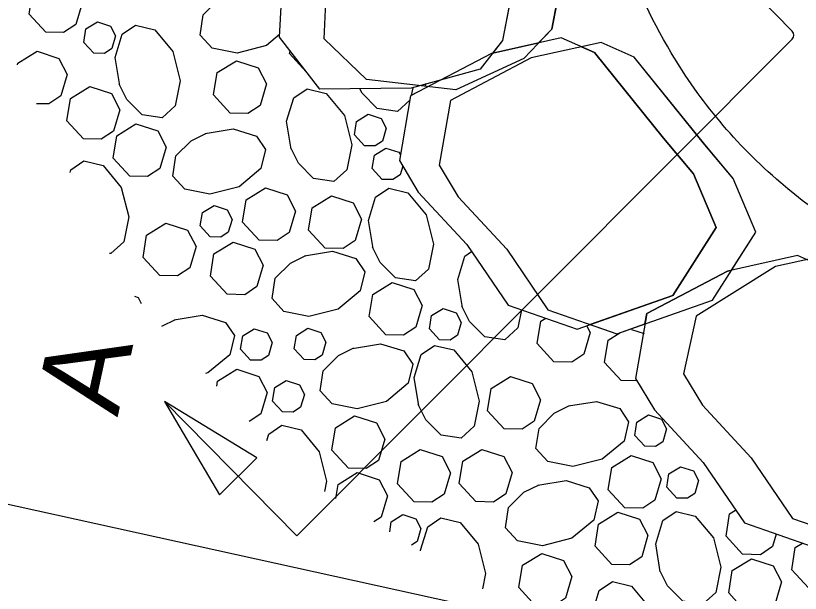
# Model space of a CAD drawing. Extents: x 2126110 to 2128246, y 1804858 to 1811658.
# Drawn here: x 2126424.9 to 2126648.9, y 1809146 to 1809310.8 of the extents above; entities that cross this region are included whole.
import ezdxf

# ---------------------------------------------------------------- set-up
doc = ezdxf.new("R2010")
doc.units = 0
for name, color, linetype in [('1', 7, 'Continuous'), ('DET-EARTH', 7, 'Continuous'), ('Old_Level_1', 7, 'Continuous'), ('Old_Level_41', 7, 'Continuous')]:
    doc.layers.add(name, color=color, linetype=linetype)

msp = doc.modelspace()

# ---------------------------------------------------------------- linework, layer by layer
at = {"layer": '1'}
for p, q in [((2126646.62, 1809306.41), (2126606.59, 1809347.5)), ((2126639.29, 1809123.78), (2126180.41, 1809224.52))]:
    msp.add_line(p, q, dxfattribs=at)
msp.add_lwpolyline([(2126467.4, 1809200.8), (2126505.18, 1809162.41), (2126646.61, 1809304.18)], dxfattribs=at)
msp.add_lwpolyline([(2126493.79, 1809184.68), (2126467.4, 1809200.8), (2126483.09, 1809174.16)], close=True, dxfattribs=at)
msp.add_arc((2126645.48, 1809305.3), 1.59, 315.0669, 44.2554, dxfattribs=at)
at = {"layer": 'DET-EARTH'}
for points in [[(2126500.75, 1809315.15), (2126505.91, 1809334.91), (2126508.16, 1809355.71), (2126522.28, 1809371.01), (2126550.92, 1809375.43), (2126570.93, 1809364.18), (2126572.45, 1809347.61), (2126569.75, 1809334.6), (2126563.89, 1809303.76), (2126557.5, 1809295.61), (2126537.84, 1809290.12), (2126537.84, 1809290.12), (2126511.78, 1809289.89), (2126500.23, 1809304.71), (2126500.75, 1809315.15)], [(2126513.47, 1809314.7), (2126516.16, 1809334.1), (2126522.49, 1809353.22), (2126533.93, 1809366.05), (2126564.43, 1809365.63), (2126581.7, 1809355.74), (2126585.18, 1809347.16), (2126583.83, 1809337.85), (2126577.97, 1809307.02), (2126569.94, 1809298.61), (2126550.56, 1809289.66), (2126550.56, 1809289.66), (2126525.08, 1809292.59), (2126512.96, 1809304.26), (2126513.47, 1809314.7)], [(2126539.84, 1809260.5), (2126553.7, 1809245.52), (2126565.5, 1809228.24), (2126585.16, 1809221.41), (2126612.51, 1809231.03), (2126624.85, 1809250.39), (2126618.37, 1809265.71), (2126609.85, 1809275.91), (2126590.13, 1809300.34), (2126580.66, 1809304.51), (2126560.72, 1809300.09), (2126560.72, 1809300.09), (2126537.65, 1809287.98), (2126534.45, 1809269.47), (2126539.84, 1809260.5)], [(2126551.21, 1809259.18), (2126565.08, 1809244.2), (2126576.87, 1809226.92), (2126596.53, 1809220.09), (2126623.88, 1809229.71), (2126636.22, 1809249.07), (2126629.74, 1809264.39), (2126621.22, 1809274.59), (2126601.5, 1809299.02), (2126592.03, 1809303.19), (2126572.09, 1809298.77), (2126572.09, 1809298.77), (2126549.02, 1809286.66), (2126545.82, 1809268.15), (2126551.21, 1809259.18)], [(2126620.99, 1809199.66), (2126634.85, 1809184.68), (2126646.65, 1809167.39), (2126666.31, 1809160.57), (2126693.66, 1809170.19), (2126706, 1809189.54), (2126699.52, 1809204.86), (2126691, 1809215.07), (2126671.28, 1809239.49), (2126661.81, 1809243.67), (2126641.87, 1809239.24), (2126641.87, 1809239.24), (2126619.16, 1809225.06), (2126615.6, 1809208.63), (2126620.99, 1809199.66)], [(2126607.26, 1809198.38), (2126621.13, 1809183.39), (2126632.93, 1809166.11), (2126652.59, 1809159.29), (2126679.94, 1809168.91), (2126692.27, 1809188.26), (2126685.8, 1809203.58), (2126677.27, 1809213.79), (2126657.56, 1809238.21), (2126648.08, 1809242.38), (2126628.15, 1809237.96), (2126628.15, 1809237.96), (2126605.07, 1809225.86), (2126601.87, 1809207.34), (2126607.26, 1809198.38)]]:
    msp.add_lwpolyline(points, dxfattribs=at)
msp.add_spline([(2126607.67, 1809405.83), (2126618.41, 1809454.94), (2126650.78, 1809501.03), (2126688.47, 1809521.66), (2126738.85, 1809522.03), (2126769.82, 1809494.4), (2126754.53, 1809276.75), (2126715.26, 1809236.01), (2126643.36, 1809263.1), (2126612.06, 1809300.25), (2126598.49, 1809332.37), (2126607.32, 1809404.19)], degree=3, dxfattribs=at)
at = {"layer": 'Old_Level_1'}
for p, q in [((2126507.92, 1809294.84), (2126507.87, 1809294.84)), ((2126538.28, 1809290.26), (2126537.85, 1809288.11)), ((2126541.9, 1809290.6), (2126542.03, 1809291.45)), ((2126466.64, 1809222.29), (2126470.5, 1809224.18)), ((2126600.67, 1809221.31), (2126604.31, 1809220.12)), ((2126602.29, 1809206.65), (2126597.79, 1809206.76))]:
    msp.add_line(p, q, dxfattribs=at)
for points in [[(2126433.48, 1809306.13), (2126428.74, 1809311.3), (2126429.75, 1809317.67), (2126435.24, 1809321.05), (2126441.46, 1809319.03), (2126443.85, 1809314.44), (2126442.04, 1809308.32), (2126438.56, 1809306.02), (2126433.49, 1809306.14)], [(2126500.26, 1809305.44), (2126496.47, 1809302.3), (2126488.1, 1809300.17), (2126480.96, 1809301.6), (2126477.57, 1809305.32), (2126478.43, 1809311.07), (2126482.79, 1809315.43), (2126487.16, 1809317.59)], [(2126447.19, 1809300.11), (2126444.35, 1809303.21), (2126444.95, 1809307.04), (2126448.25, 1809309.07), (2126451.98, 1809307.85), (2126453.41, 1809305.1), (2126452.32, 1809301.43), (2126450.24, 1809300.05), (2126447.2, 1809300.12)], [(2126454.6, 1809290.94), (2126453.29, 1809298.95), (2126455.35, 1809305.6), (2126459.12, 1809308.15), (2126464.59, 1809306.84), (2126469.77, 1809300.59), (2126471.89, 1809292.22), (2126470.46, 1809285.08), (2126466.74, 1809281.69), (2126460.99, 1809282.56), (2126456.63, 1809286.91), (2126454.48, 1809291.28)], [(2126425.47, 1809296.82), (2126425.54, 1809297.29), (2126431.03, 1809300.67), (2126437.25, 1809298.65), (2126439.63, 1809294.05), (2126437.82, 1809287.94), (2126434.35, 1809285.64), (2126430.87, 1809285.72)], [(2126507.87, 1809294.84), (2126503.12, 1809300.01), (2126503.25, 1809300.83)], [(2126486.15, 1809283.06), (2126481.4, 1809288.23), (2126482.42, 1809294.6), (2126487.91, 1809297.98), (2126494.12, 1809295.96), (2126496.51, 1809291.37), (2126494.7, 1809285.25), (2126491.23, 1809282.95), (2126486.15, 1809283.07)], [(2126444.27, 1809275.7), (2126439.53, 1809280.87), (2126440.54, 1809287.24), (2126446.04, 1809290.62), (2126452.25, 1809288.6), (2126454.63, 1809284.01), (2126452.83, 1809277.89), (2126449.35, 1809275.59), (2126444.27, 1809275.7)], [(2126503.58, 1809272.75), (2126502.27, 1809280.76), (2126504.33, 1809287.4), (2126508.09, 1809289.95), (2126513.57, 1809288.65), (2126518.74, 1809282.4), (2126520.87, 1809274.03), (2126519.44, 1809266.88), (2126515.72, 1809263.5), (2126509.97, 1809264.36), (2126505.61, 1809268.72), (2126503.45, 1809273.09)], [(2126537.43, 1809286.72), (2126533.88, 1809283.49), (2126528.13, 1809284.36), (2126523.78, 1809288.71), (2126523.14, 1809289.99)], [(2126524.49, 1809273.74), (2126521.64, 1809276.84), (2126522.25, 1809280.66), (2126525.54, 1809282.69), (2126529.27, 1809281.48), (2126530.7, 1809278.72), (2126529.62, 1809275.05), (2126527.54, 1809273.67), (2126524.49, 1809273.74)], [(2126457.48, 1809265.04), (2126452.74, 1809270.21), (2126453.75, 1809276.58), (2126459.24, 1809279.96), (2126465.46, 1809277.94), (2126467.84, 1809273.35), (2126466.04, 1809267.24), (2126462.56, 1809264.93), (2126457.48, 1809265.05)], [(2126479.02, 1809277.2), (2126487.03, 1809278.52), (2126493.68, 1809276.45), (2126496.23, 1809272.69), (2126494.92, 1809267.21), (2126488.68, 1809262.04), (2126480.3, 1809259.91), (2126473.16, 1809261.34), (2126469.78, 1809265.06), (2126470.64, 1809270.81), (2126474.99, 1809275.17), (2126479.36, 1809277.33)], [(2126529.55, 1809264.11), (2126526.7, 1809267.21), (2126527.31, 1809271.04), (2126530.6, 1809273.06), (2126534.33, 1809271.85), (2126534.73, 1809271.1)], [(2126440.42, 1809266.12), (2126440.64, 1809266.85), (2126444.4, 1809269.4), (2126449.88, 1809268.1), (2126455.06, 1809261.85), (2126457.18, 1809253.48), (2126455.75, 1809246.33), (2126452.03, 1809242.95), (2126451.68, 1809243)], [(2126535.4, 1809267.88), (2126534.68, 1809265.43), (2126532.6, 1809264.05), (2126529.55, 1809264.12)], [(2126494.45, 1809246.78), (2126489.71, 1809251.95), (2126490.72, 1809258.31), (2126496.22, 1809261.7), (2126502.43, 1809259.68), (2126504.82, 1809255.08), (2126503.01, 1809248.97), (2126499.54, 1809246.67), (2126494.46, 1809246.78)], [(2126526.92, 1809244.41), (2126525.6, 1809252.42), (2126527.67, 1809259.06), (2126531.43, 1809261.61), (2126536.91, 1809260.31), (2126542.08, 1809254.06), (2126544.21, 1809245.69), (2126542.78, 1809238.54), (2126539.06, 1809235.16), (2126533.31, 1809236.02), (2126528.95, 1809240.38), (2126526.79, 1809244.75)], [(2126513.28, 1809244.5), (2126508.53, 1809249.67), (2126509.55, 1809256.04), (2126515.04, 1809259.42), (2126521.26, 1809257.4), (2126523.64, 1809252.81), (2126521.83, 1809246.69), (2126518.36, 1809244.39), (2126513.28, 1809244.51)], [(2126480.47, 1809247.73), (2126477.62, 1809250.83), (2126478.23, 1809254.65), (2126481.53, 1809256.68), (2126485.26, 1809255.47), (2126486.69, 1809252.71), (2126485.6, 1809249.05), (2126483.52, 1809247.66), (2126480.47, 1809247.73)], [(2126466.03, 1809236.7), (2126461.28, 1809241.87), (2126462.3, 1809248.24), (2126467.79, 1809251.62), (2126474, 1809249.6), (2126476.39, 1809245.01), (2126474.58, 1809238.89), (2126471.11, 1809236.59), (2126466.03, 1809236.7)], [(2126485.25, 1809231.35), (2126480.51, 1809236.51), (2126481.52, 1809242.88), (2126487.01, 1809246.26), (2126493.23, 1809244.24), (2126495.61, 1809239.65), (2126493.8, 1809233.53), (2126490.33, 1809231.23), (2126485.25, 1809231.35)], [(2126507.36, 1809242.29), (2126515.37, 1809243.6), (2126522.02, 1809241.53), (2126524.57, 1809237.77), (2126523.26, 1809232.3), (2126517.01, 1809227.12), (2126508.64, 1809225), (2126501.5, 1809226.43), (2126498.11, 1809230.15), (2126498.97, 1809235.9), (2126503.33, 1809240.26), (2126507.7, 1809242.41)], [(2126552.43, 1809227.6), (2126551.12, 1809235.61), (2126553.18, 1809242.26), (2126555.06, 1809243.53)], [(2126530.59, 1809219.79), (2126525.85, 1809224.96), (2126526.86, 1809231.33), (2126532.35, 1809234.71), (2126538.57, 1809232.69), (2126540.95, 1809228.1), (2126539.15, 1809221.99), (2126535.67, 1809219.68), (2126530.59, 1809219.8)], [(2126458.86, 1809230.77), (2126459.83, 1809230.46), (2126460.72, 1809228.74)], [(2126545.88, 1809218.34), (2126543.03, 1809221.44), (2126543.64, 1809225.26), (2126546.94, 1809227.29), (2126550.67, 1809226.08), (2126552.1, 1809223.32), (2126551.01, 1809219.65), (2126548.93, 1809218.27), (2126545.88, 1809218.34)], [(2126569.32, 1809226.91), (2126568.29, 1809221.74), (2126564.57, 1809218.36), (2126558.82, 1809219.22), (2126554.46, 1809223.57), (2126552.3, 1809227.94)], [(2126470.16, 1809224.06), (2126478.17, 1809225.37), (2126484.81, 1809223.31), (2126487.36, 1809219.54), (2126486.06, 1809214.07), (2126479.81, 1809208.89), (2126479.09, 1809208.71)], [(2126578.56, 1809212.11), (2126573.82, 1809217.28), (2126574.84, 1809223.64), (2126576.24, 1809224.51)], [(2126491.95, 1809212.57), (2126489.11, 1809215.67), (2126489.72, 1809219.49), (2126493.01, 1809221.52), (2126496.74, 1809220.3), (2126498.17, 1809217.55), (2126497.08, 1809213.88), (2126495, 1809212.5), (2126491.96, 1809212.57)], [(2126507.28, 1809212.7), (2126504.43, 1809215.8), (2126505.04, 1809219.62), (2126508.34, 1809221.65), (2126512.06, 1809220.44), (2126513.49, 1809217.69), (2126512.41, 1809214.02), (2126510.33, 1809212.63), (2126507.28, 1809212.7)], [(2126587.96, 1809222.28), (2126588.93, 1809220.42), (2126587.12, 1809214.3), (2126583.64, 1809212), (2126578.57, 1809212.11)], [(2126597.79, 1809206.75), (2126593.04, 1809211.92), (2126594.06, 1809218.29), (2126597.39, 1809220.34)], [(2126521.08, 1809215.92), (2126529.09, 1809217.24), (2126535.74, 1809215.17), (2126538.29, 1809211.41), (2126536.99, 1809205.94), (2126530.74, 1809200.76), (2126522.36, 1809198.64), (2126515.22, 1809200.06), (2126511.84, 1809203.79), (2126512.7, 1809209.54), (2126517.05, 1809213.89), (2126521.42, 1809216.05)], [(2126539.96, 1809199.56), (2126538.65, 1809207.57), (2126540.71, 1809214.21), (2126544.47, 1809216.76), (2126549.95, 1809215.46), (2126555.12, 1809209.21), (2126557.25, 1809200.84), (2126555.82, 1809193.69), (2126552.1, 1809190.31), (2126546.35, 1809191.17), (2126541.99, 1809195.53), (2126539.83, 1809199.9)], [(2126482.35, 1809205.16), (2126482.57, 1809206.55), (2126488.07, 1809209.94), (2126494.28, 1809207.91), (2126496.67, 1809203.32), (2126494.86, 1809197.21), (2126491.61, 1809195.06)], [(2126564.39, 1809192.97), (2126559.65, 1809198.13), (2126560.66, 1809204.51), (2126566.15, 1809207.89), (2126572.37, 1809205.87), (2126574.76, 1809201.27), (2126572.95, 1809195.16), (2126569.48, 1809192.86), (2126564.4, 1809192.97)], [(2126501.12, 1809197.79), (2126498.27, 1809200.89), (2126498.88, 1809204.71), (2126502.17, 1809206.74), (2126505.9, 1809205.52), (2126507.33, 1809202.77), (2126506.25, 1809199.1), (2126504.16, 1809197.72), (2126501.12, 1809197.79)], [(2126582.7, 1809199.47), (2126590.71, 1809200.78), (2126597.35, 1809198.72), (2126599.9, 1809194.95), (2126598.6, 1809189.48), (2126592.35, 1809184.3), (2126583.97, 1809182.18), (2126576.83, 1809183.61), (2126573.45, 1809187.33), (2126574.31, 1809193.08), (2126578.66, 1809197.44), (2126583.03, 1809199.59)], [(2126519.91, 1809181.74), (2126515.16, 1809186.9), (2126516.17, 1809193.27), (2126521.67, 1809196.66), (2126527.88, 1809194.64), (2126530.27, 1809190.04), (2126528.46, 1809183.93), (2126524.98, 1809181.63), (2126519.91, 1809181.74)], [(2126604.49, 1809187.98), (2126601.65, 1809191.07), (2126602.25, 1809194.9), (2126605.55, 1809196.93), (2126609.28, 1809195.71), (2126610.71, 1809192.96), (2126609.62, 1809189.29), (2126607.54, 1809187.91), (2126604.49, 1809187.98)], [(2126496.6, 1809189.62), (2126497.15, 1809191.41), (2126500.92, 1809193.96), (2126506.39, 1809192.66), (2126511.57, 1809186.41), (2126513.69, 1809178.03), (2126513.09, 1809175.04)], [(2126538.66, 1809172.14), (2126533.92, 1809177.3), (2126534.93, 1809183.67), (2126540.42, 1809187.05), (2126546.64, 1809185.03), (2126549.02, 1809180.44), (2126547.22, 1809174.33), (2126543.74, 1809172.02), (2126538.66, 1809172.14)], [(2126556.25, 1809172.18), (2126551.51, 1809177.34), (2126552.53, 1809183.71), (2126558.01, 1809187.09), (2126564.23, 1809185.07), (2126566.61, 1809180.48), (2126564.81, 1809174.37), (2126561.34, 1809172.06), (2126556.25, 1809172.18)], [(2126598.84, 1809170.42), (2126594.1, 1809175.59), (2126595.11, 1809181.96), (2126600.6, 1809185.34), (2126606.82, 1809183.32), (2126609.2, 1809178.73), (2126607.4, 1809172.61), (2126603.92, 1809170.31), (2126598.84, 1809170.43)], [(2126516.31, 1809173.07), (2126516.95, 1809177.09), (2126522.44, 1809180.47), (2126528.66, 1809178.45), (2126531.04, 1809173.86), (2126529.23, 1809167.74), (2126527.18, 1809166.39)], [(2126613.65, 1809173.19), (2126610.81, 1809176.29), (2126611.41, 1809180.12), (2126614.71, 1809182.14), (2126618.44, 1809180.93), (2126619.87, 1809178.18), (2126618.78, 1809174.51), (2126616.7, 1809173.13), (2126613.65, 1809173.2)], [(2126574.02, 1809176.89), (2126582.03, 1809178.2), (2126588.67, 1809176.13), (2126591.22, 1809172.37), (2126589.92, 1809166.9), (2126583.67, 1809161.72), (2126575.29, 1809159.6), (2126568.15, 1809161.02), (2126564.77, 1809164.75), (2126565.63, 1809170.5), (2126569.98, 1809174.85), (2126574.35, 1809177.01)], [(2126595.06, 1809154.27), (2126590.31, 1809159.43), (2126591.33, 1809165.8), (2126596.82, 1809169.18), (2126603.04, 1809167.16), (2126605.42, 1809162.57), (2126603.62, 1809156.46), (2126600.14, 1809154.15), (2126595.06, 1809154.27)], [(2126608.94, 1809152.16), (2126607.63, 1809160.18), (2126609.69, 1809166.82), (2126613.45, 1809169.37), (2126618.93, 1809168.07), (2126624.11, 1809161.82), (2126626.23, 1809153.44), (2126624.8, 1809146.3), (2126621.08, 1809142.92), (2126615.33, 1809143.78), (2126610.97, 1809148.13), (2126608.81, 1809152.5)], [(2126632.44, 1809157.15), (2126627.7, 1809162.31), (2126628.71, 1809168.68), (2126630.45, 1809169.75)], [(2126531.7, 1809163.61), (2126532.15, 1809166.46), (2126535.44, 1809168.49), (2126539.17, 1809167.28), (2126540.6, 1809164.52), (2126539.52, 1809160.85), (2126537.92, 1809159.79)], [(2126540.51, 1809158.19), (2126540.48, 1809158.38), (2126542.55, 1809165.02), (2126546.31, 1809167.57), (2126551.78, 1809166.27), (2126556.96, 1809160.02), (2126559.08, 1809151.64), (2126558.22, 1809147.31)], [(2126642.06, 1809162.94), (2126641, 1809159.34), (2126637.52, 1809157.03), (2126632.44, 1809157.15)], [(2126651.2, 1809147.54), (2126646.45, 1809152.71), (2126647.47, 1809159.08), (2126649.54, 1809160.35)], [(2126573.34, 1809142.49), (2126568.59, 1809147.65), (2126569.61, 1809154.02), (2126575.1, 1809157.41), (2126581.32, 1809155.39), (2126583.7, 1809150.79), (2126581.9, 1809144.68), (2126578.42, 1809142.38), (2126573.34, 1809142.49)], [(2126633.21, 1809140.96), (2126628.47, 1809146.13), (2126629.49, 1809152.5), (2126634.98, 1809155.88), (2126641.19, 1809153.86), (2126643.58, 1809149.27), (2126641.77, 1809143.15), (2126638.3, 1809140.85), (2126633.22, 1809140.97)], [(2126590.77, 1809132.17), (2126589.46, 1809140.18), (2126591.53, 1809146.83), (2126595.29, 1809149.38), (2126600.76, 1809148.07), (2126605.94, 1809141.82), (2126608.06, 1809133.45), (2126606.63, 1809126.31), (2126602.91, 1809122.92), (2126597.16, 1809123.78), (2126592.8, 1809128.14), (2126590.65, 1809132.51)]]:
    msp.add_lwpolyline(points, dxfattribs=at)
at = {"layer": 'Old_Level_41'}
for p, q in [((2126577.97, 1809307.02), (2126583.83, 1809337.85)), ((2126569.76, 1809334.6), (2126563.89, 1809303.76)), ((2126574.21, 1809303.08), (2126577.97, 1809307.02)), ((2126563.89, 1809303.76), (2126561.07, 1809300.16)), ((2126561.07, 1809300.16), (2126574.21, 1809303.08)), ((2126592.03, 1809303.19), (2126586.46, 1809301.95)), ((2126586.46, 1809301.95), (2126590.13, 1809300.34)), ((2126601.51, 1809299.02), (2126592.03, 1809303.19)), ((2126590.13, 1809300.34), (2126609.85, 1809275.91)), ((2126621.23, 1809274.59), (2126601.51, 1809299.02)), ((2126609.85, 1809275.91), (2126618.37, 1809265.71)), ((2126629.74, 1809264.39), (2126621.23, 1809274.59)), ((2126618.37, 1809265.71), (2126624.85, 1809250.39)), ((2126636.22, 1809249.07), (2126629.74, 1809264.39)), ((2126624.85, 1809250.39), (2126612.51, 1809231.03)), ((2126629.3, 1809238.21), (2126636.22, 1809249.07)), ((2126605.07, 1809225.86), (2126628.15, 1809237.96)), ((2126628.15, 1809237.96), (2126629.3, 1809238.21)), ((2126612.51, 1809231.03), (2126588.92, 1809222.73)), ((2126604.56, 1809222.91), (2126605.07, 1809225.86)), ((2126588.92, 1809222.73), (2126596.54, 1809220.09)), ((2126596.54, 1809220.09), (2126604.56, 1809222.91))]:
    msp.add_line(p, q, dxfattribs=at)
for points in [[(2126500.75, 1809315.15), (2126505.91, 1809334.91), (2126508.16, 1809355.71), (2126522.28, 1809371.01), (2126550.92, 1809375.43), (2126570.93, 1809364.18), (2126572.45, 1809347.61), (2126569.75, 1809334.6), (2126563.89, 1809303.76), (2126557.5, 1809295.61), (2126537.84, 1809290.12), (2126537.84, 1809290.12), (2126511.78, 1809289.89), (2126500.23, 1809304.71), (2126500.75, 1809315.15)], [(2126539.84, 1809260.5), (2126553.7, 1809245.52), (2126565.5, 1809228.24), (2126585.16, 1809221.41), (2126612.51, 1809231.03), (2126624.85, 1809250.39), (2126618.37, 1809265.71), (2126609.85, 1809275.91), (2126590.13, 1809300.34), (2126580.66, 1809304.51), (2126560.72, 1809300.09), (2126560.72, 1809300.09), (2126537.65, 1809287.98), (2126534.45, 1809269.47), (2126539.84, 1809260.5)], [(2126607.26, 1809198.38), (2126621.13, 1809183.39), (2126632.93, 1809166.11), (2126652.59, 1809159.29), (2126679.94, 1809168.91), (2126692.27, 1809188.26), (2126685.8, 1809203.58), (2126677.27, 1809213.79), (2126657.56, 1809238.21), (2126648.08, 1809242.38), (2126628.15, 1809237.96), (2126628.15, 1809237.96), (2126605.07, 1809225.86), (2126601.87, 1809207.34), (2126607.26, 1809198.38)]]:
    msp.add_lwpolyline(points, dxfattribs=at)

# ---------------------------------------------------------------- texts
at = {"layer": 'DET-EARTH'}
msp.add_text('A', height=23.92, rotation=77.8263, dxfattribs=at).set_placement((2126453.99, 1809196.15))

doc.saveas('drawing.dxf')
